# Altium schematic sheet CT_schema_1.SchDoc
size 467 x 456 mm
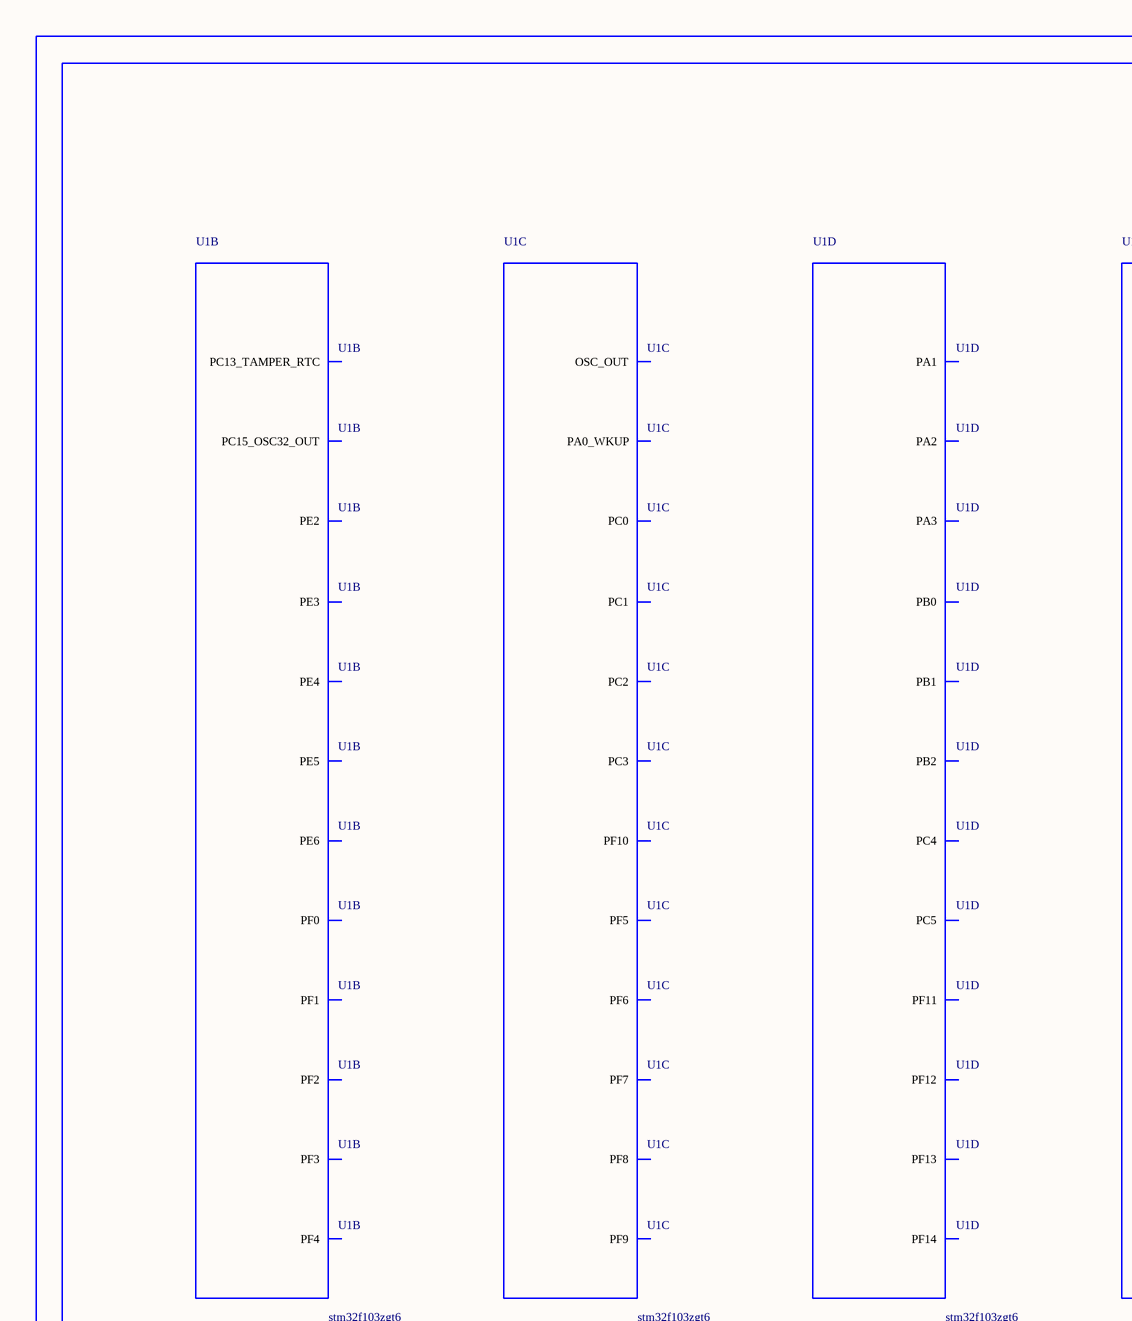
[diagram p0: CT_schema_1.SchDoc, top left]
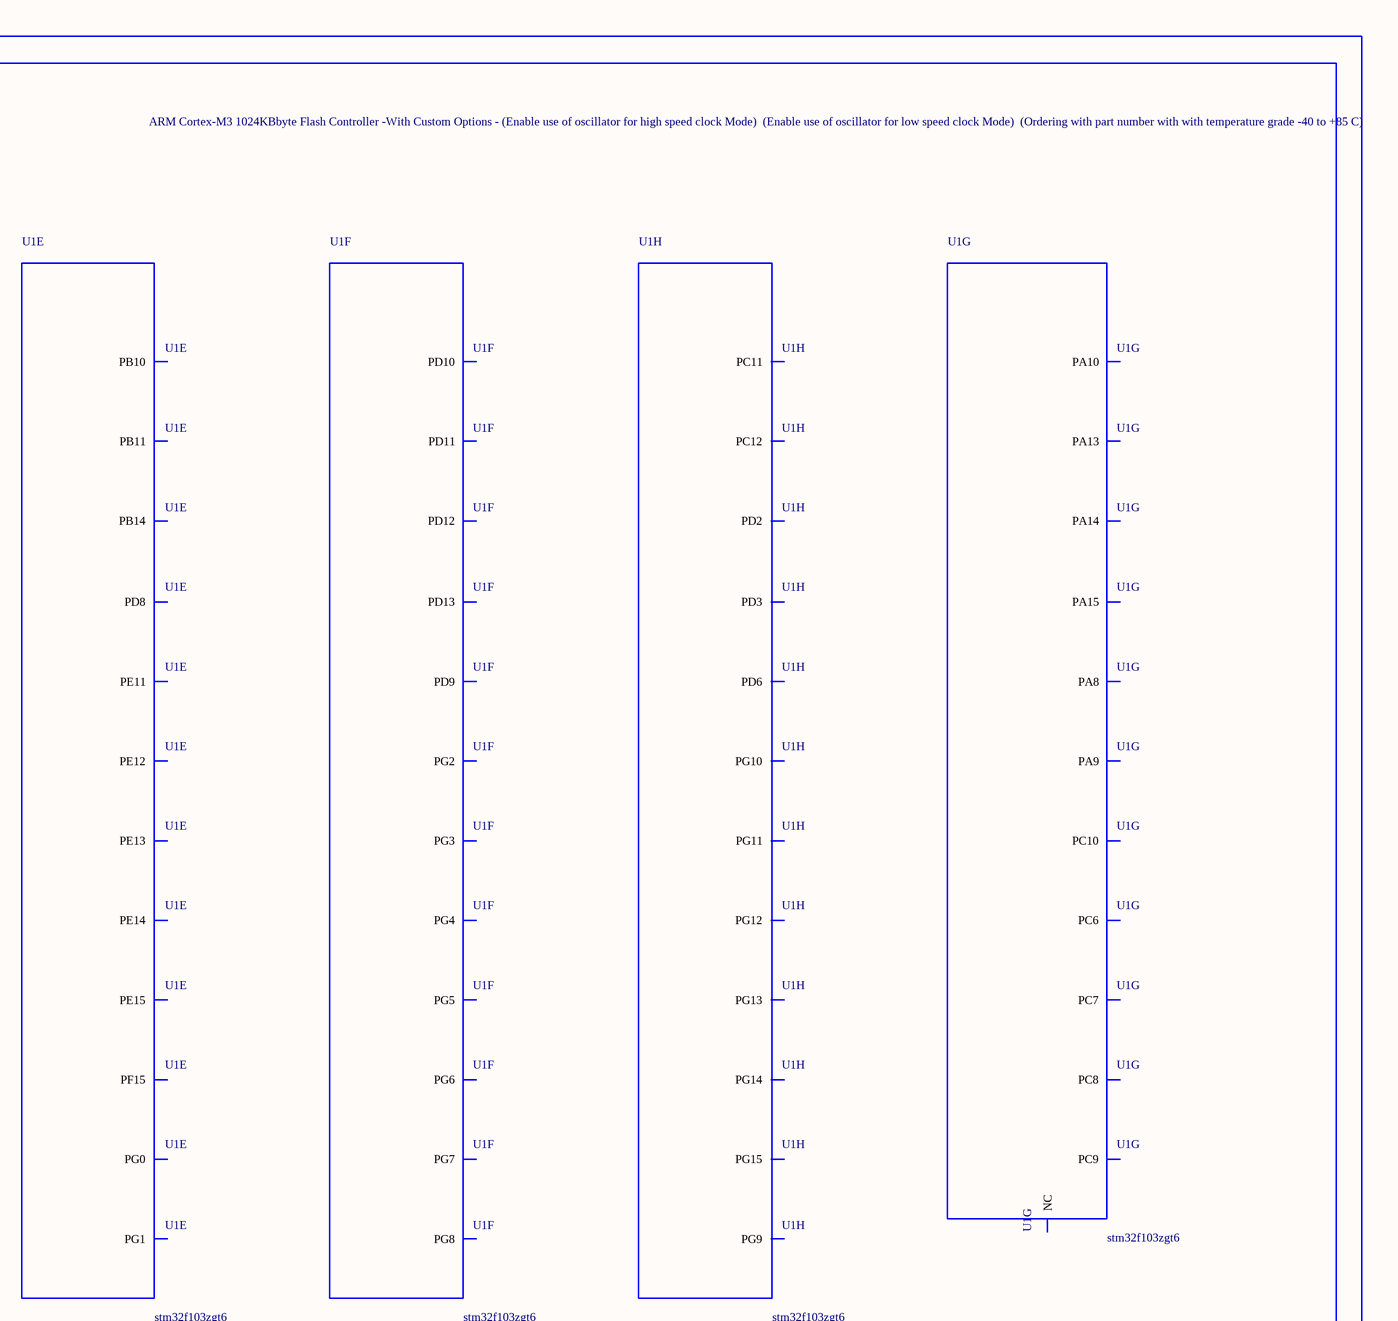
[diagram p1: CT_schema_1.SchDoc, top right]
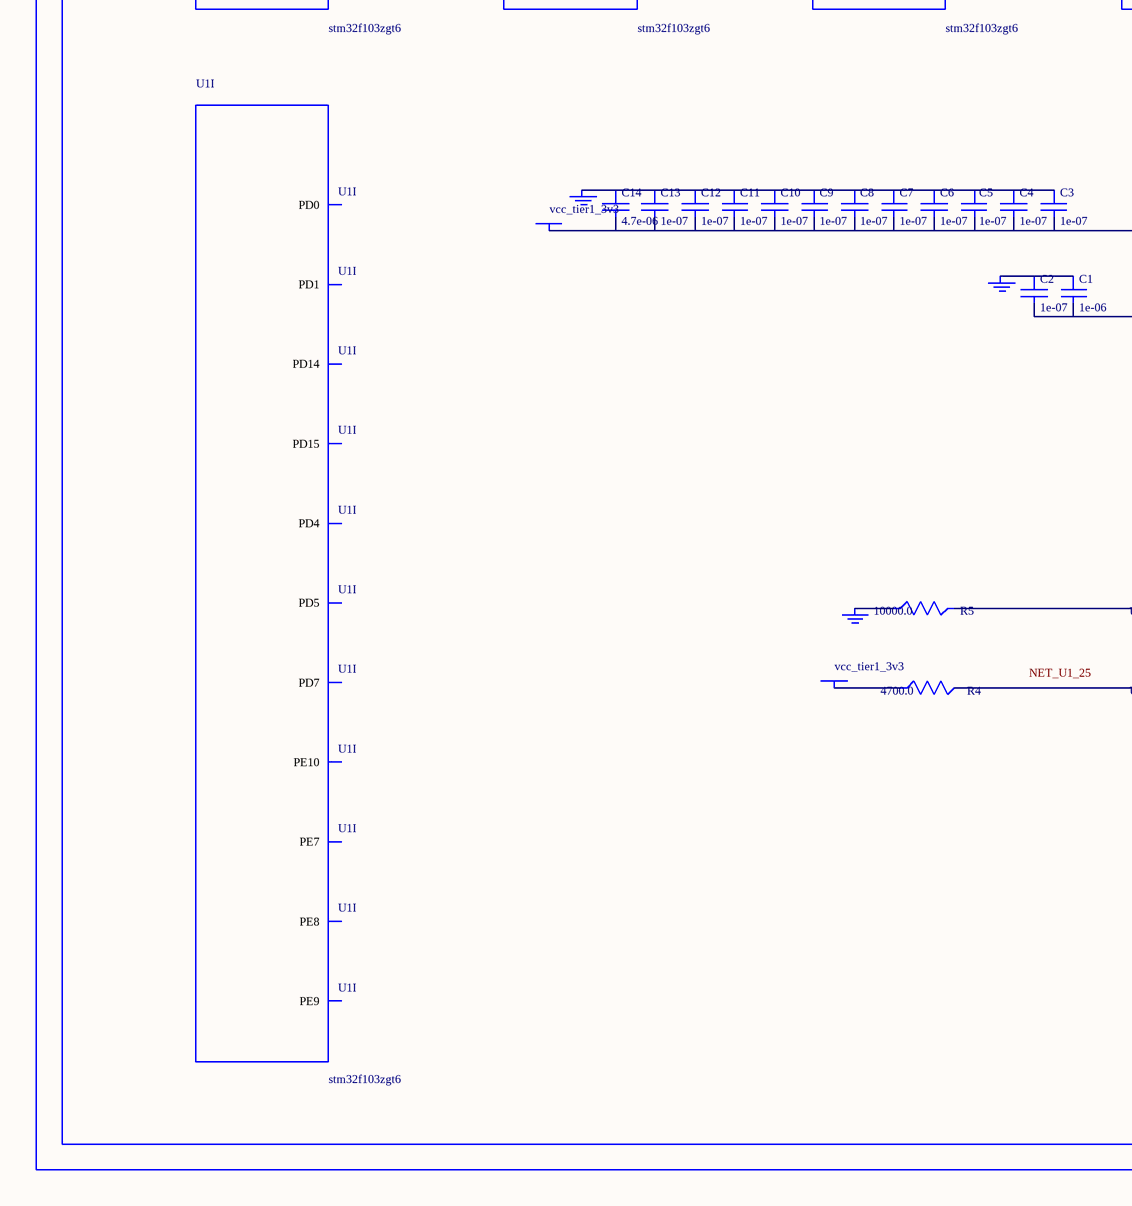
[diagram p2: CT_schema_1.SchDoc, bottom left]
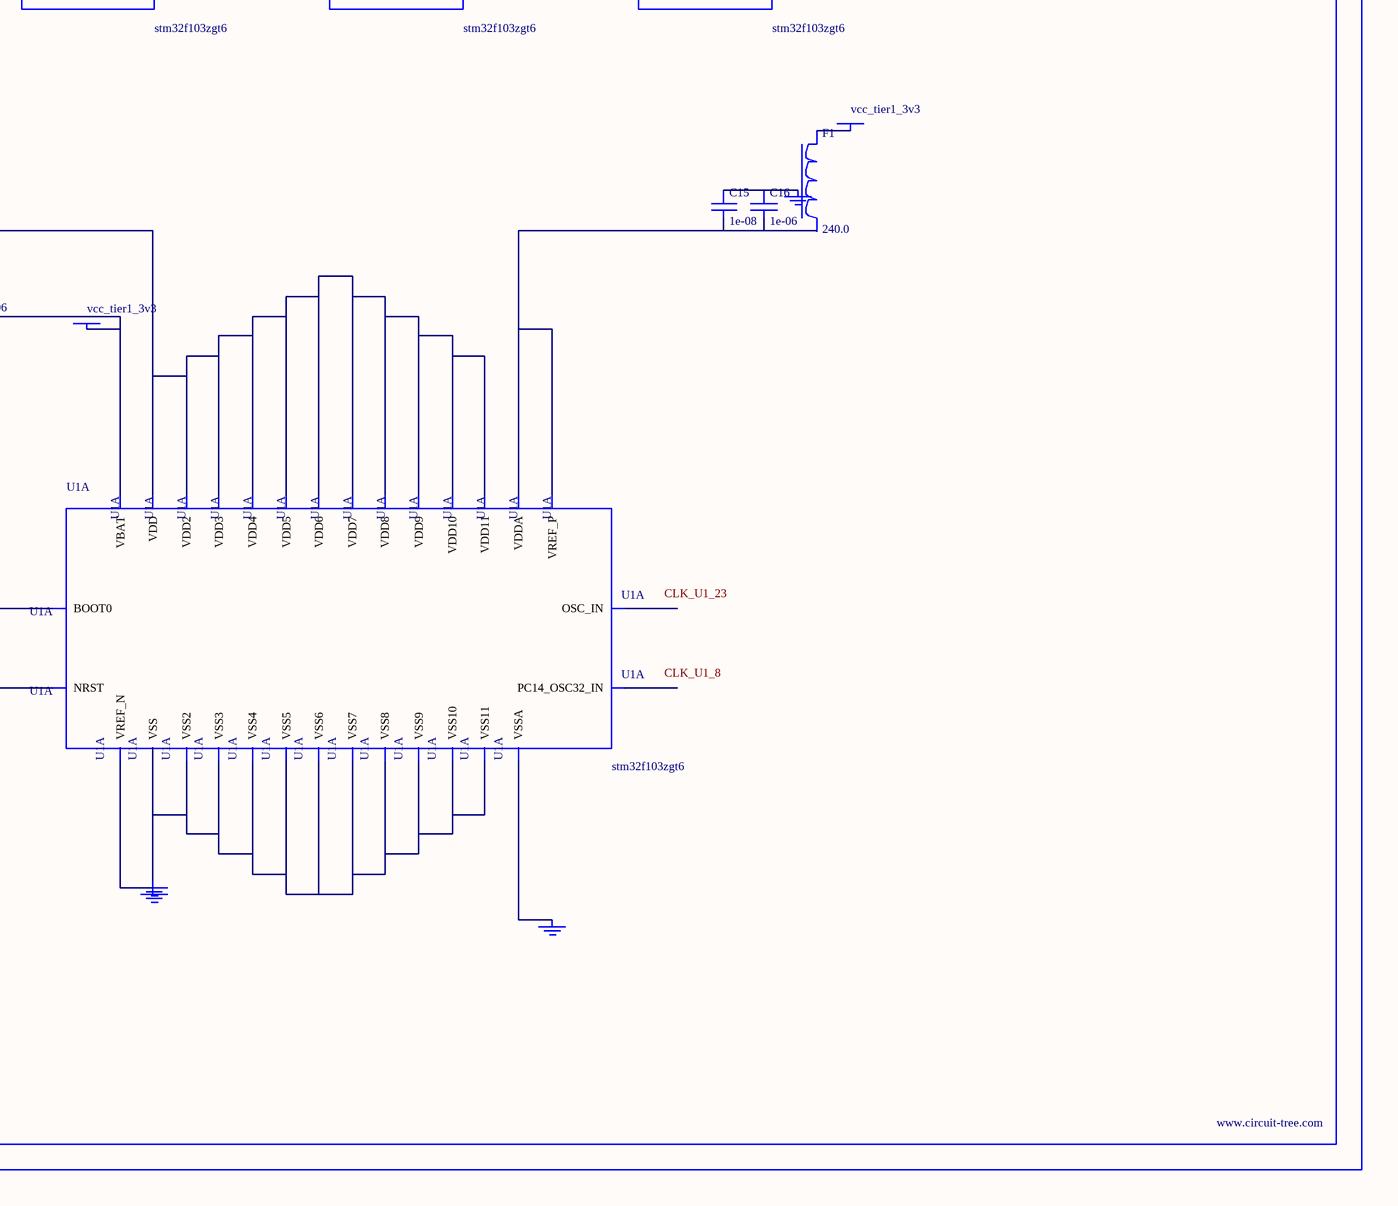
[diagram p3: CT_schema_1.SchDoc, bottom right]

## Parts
BORDER0  (no value)
C1  1e-06  [C0603]
C2  1e-07  [C0603]
C3  1e-07  [C0603]
C4  1e-07  [C0603]
C5  1e-07  [C0603]
C6  1e-07  [C0603]
C7  1e-07  [C0603]
C8  1e-07  [C0603]
C9  1e-07  [C0603]
C10  1e-07  [C0603]
C11  1e-07  [C0603]
C12  1e-07  [C0603]
C13  1e-07  [C0603]
C14  4.7e-06  [C0603]
C15  1e-08  [C0603]
C16  1e-06  [C0603]
F1  240.0  [L0603]
GND_INSTANCE_0_0  (no value)
GND_INSTANCE_0_1  (no value)
GND_INSTANCE_0_2  (no value)
GND_INSTANCE_0_3  (no value)
GND_INSTANCE_0_4  (no value)
GND_INSTANCE_0_5  (no value)
GND_INSTANCE_0_6  (no value)
POWER_INSTANCE_0_0  vcc_tier1_3v3
POWER_INSTANCE_0_1  vcc_tier1_3v3
POWER_INSTANCE_0_2  vcc_tier1_3v3
POWER_INSTANCE_0_3  vcc_tier1_3v3
R4  4700.0  [R0603]
R5  10000.0  [R0603]
U1  stm32f103zgt6  [LQFP144]  (parts A,B,C,D,E,F,G,H,I of 12)

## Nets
NetC1_1: C1.1 C2.1 GND_INSTANCE_0_0.0(GND)
NetC1_2: C1.2 C2.2 POWER_INSTANCE_0_0.0(PWR) U1.6(VBAT)
NetC3_1: C3.1 C4.1 C5.1 C6.1 C7.1 C8.1 C9.1 C10.1 C11.1 C12.1 C13.1 C14.1 GND_INSTANCE_0_1.0(GND)
NetC3_2: C3.2 C4.2 C5.2 C6.2 C7.2 C8.2 C9.2 C10.2 C11.2 C12.2 C13.2 C14.2 POWER_INSTANCE_0_1.0(PWR) U1.17(VDD) U1.39(VDD2) U1.52(VDD3) U1.62(VDD4) U1.72(VDD5) U1.84(VDD6) U1.95(VDD7) U1.108(VDD8) U1.121(VDD9) U1.131(VDD10) U1.144(VDD11)
NetC15_1: C15.1 C16.1 GND_INSTANCE_0_4.0(GND)
NetC15_2: C15.2 C16.2 U1.32(VREF_P) U1.33(VDDA)
NetF1_1: F1.1 POWER_INSTANCE_0_2.0(PWR)
NetGND_INSTANCE_0_2_0: GND_INSTANCE_0_2.0(GND) U1.30(VSSA)
NetGND_INSTANCE_0_3_0: GND_INSTANCE_0_3.0(GND) U1.31(VREF_N)
NetGND_INSTANCE_0_5_0: GND_INSTANCE_0_5.0(GND) R5.1
NetGND_INSTANCE_0_6_0: GND_INSTANCE_0_6.0(GND) U1.16(VSS) U1.38(VSS2) U1.51(VSS3) U1.61(VSS4) U1.71(VSS5) U1.83(VSS6) U1.94(VSS7) U1.107(VSS8) U1.120(VSS9) U1.130(VSS10) U1.143(VSS11)
NetPOWER_INSTANCE_0_3_0: POWER_INSTANCE_0_3.0(PWR) R4.1
NetR4_2: R4.2 U1.25(NRST)
NetR5_2: R5.2 U1.138(BOOT0)

Not connected (* = marked no-connect by the designer): F1 2; U1 1(PE2) 2(PE3) 3(PE4) 4(PE5) 5(PE6) 7(PC13_TAMPER_RTC) 8(PC14_OSC32_IN) 9(PC15_OSC32_OUT) 10(PF0) 11(PF1) 12(PF2) 13(PF3) 14(PF4) 15(PF5) 18(PF6) 19(PF7) 20(PF8) 21(PF9) 22(PF10) 23(OSC_IN) 24(OSC_OUT) 26(PC0) 27(PC1) 28(PC2) 29(PC3) 34(PA0_WKUP) 35(PA1) 36(PA2) 37(PA3) 44(PC4) 45(PC5) 46(PB0) 47(PB1) 48(PB2) 49(PF11) 50(PF12) 53(PF13) 54(PF14) 55(PF15) 56(PG0) 57(PG1) 58(PE7) 59(PE8) 60(PE9) 63(PE10) 64(PE11) 65(PE12) 66(PE13) 67(PE14) 68(PE15) 69(PB10) 70(PB11) 75(PB14) 77(PD8) 78(PD9) 79(PD10) 80(PD11) 81(PD12) 82(PD13) 85(PD14) 86(PD15) 87(PG2) 88(PG3) 89(PG4) 90(PG5) 91(PG6) 92(PG7) 93(PG8) 96(PC6) 97(PC7) 98(PC8) 99(PC9) 100(PA8) 101(PA9) 102(PA10) 105(PA13) 106(NC) 109(PA14) 110(PA15) 111(PC10) 112(PC11) 113(PC12) 114(PD0) 115(PD1) 116(PD2) 117(PD3) 118(PD4) 119(PD5) 122(PD6) 123(PD7) 124(PG9) 125(PG10) 126(PG11) 127(PG12) 128(PG13) 129(PG14) 132(PG15)

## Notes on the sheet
- Labels drawn without touching a wire or pin: CLK_U1_8, CLK_U1_23, NET_U1_25

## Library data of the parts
BORDER0 = BORDER_PAGE0
C1 C16 = C0603C105K3RACTU
C2-C13 = 06035C104K4Z2A
C14 = GRM188R6YA475KE15D
C15 = 06035C103K4Z2A
F1 = Z0603C241ASMST
GND_INSTANCE_0_0-GND_INSTANCE_0_6 = GND
POWER_INSTANCE_0_0-POWER_INSTANCE_0_3 = PWR
R4 = RC0603JR-074K7L
R5 = RC0603JR-0710KL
